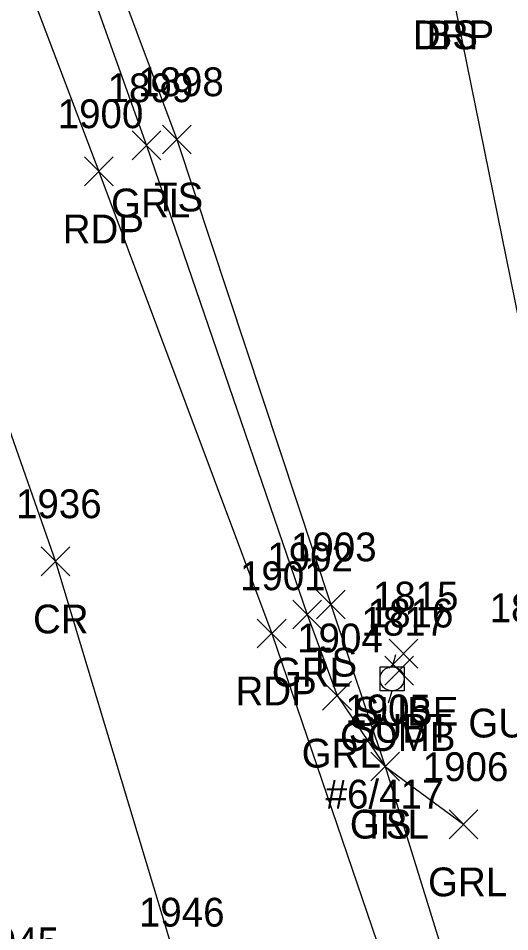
# Model space of a CAD drawing. Extents: x 1651305 to 1654558, y 539481 to 548441.
# Drawn here: x 1654361.1 to 1654395.2, y 544544.9 to 544608.3 of the extents above; entities that cross this region are included whole.
import ezdxf

# ---------------------------------------------------------------- set-up
doc = ezdxf.new("R2010")
doc.units = 0
for name, color, linetype in [('L_A', 7, 'Continuous'), ('L_I', 7, 'Continuous'), ('L_TIC', 7, 'Continuous'), ('LELB', 7, 'Continuous'), ('P_A', 7, 'Continuous'), ('P_I', 7, 'Continuous'), ('P_TIC', 7, 'Continuous'), ('PET', 7, 'Continuous'), ('PRC', 7, 'Continuous'), ('R_A', 7, 'Continuous'), ('R_I', 7, 'Continuous'), ('R_TIC', 7, 'Continuous'), ('RDP', 7, 'Continuous'), ('RGR', 7, 'Continuous'), ('U_A', 7, 'Continuous'), ('U_C', 7, 'Continuous'), ('U_I', 7, 'Continuous'), ('U_TIC', 7, 'Continuous'), ('UP', 7, 'Continuous')]:
    doc.layers.add(name, color=color, linetype=linetype)

msp = doc.modelspace()

# ---------------------------------------------------------------- linework, layer by layer
at = {"layer": 'L_TIC'}
for points in [[(1654371.116, 544598.924), (1654373.116, 544600.924)], [(1654373.116, 544598.924), (1654371.116, 544600.924)], [(1654381.811, 544566.633), (1654383.811, 544568.633)], [(1654383.811, 544566.633), (1654381.811, 544568.633)], [(1654385.584, 544555.384), (1654387.584, 544557.384)], [(1654387.584, 544555.384), (1654385.584, 544557.384)]]:
    msp.add_lwpolyline(points, dxfattribs=at)
at = {"layer": 'LELB'}
msp.add_lwpolyline([(1654360.198, 544631.754), (1654372.116, 544599.924), (1654382.811, 544567.633), (1654386.584, 544556.384), (1654391.723, 544539.804)], dxfattribs=at)
at = {"layer": 'P_TIC'}
for points in [[(1654365.692, 544596.705), (1654367.692, 544598.705)], [(1654367.692, 544596.705), (1654365.692, 544598.705)], [(1654362.685, 544569.628), (1654364.685, 544571.628)], [(1654364.685, 544569.628), (1654362.685, 544571.628)], [(1654377.699, 544564.627), (1654379.699, 544566.627)], [(1654379.699, 544564.627), (1654377.699, 544566.627)]]:
    msp.add_lwpolyline(points, dxfattribs=at)
at = {"layer": 'PET'}
msp.add_lwpolyline([(1654345.042, 544588.36), (1654350.59, 544607.191), (1654356.582, 544624.309), (1654366.692, 544597.705), (1654378.699, 544565.627), (1654388.798, 544536.019), (1654394.392, 544506.433), (1654399.121, 544481.008), (1654401.125, 544462.893), (1654401.531, 544436.346), (1654401.825, 544421.309), (1654397.366, 544359.696), (1654394.392, 544336.586), (1654391.404, 544308.963), (1654388.941, 544290.736), (1654386.845, 544274.06), (1654380.974, 544229.445), (1654377.749, 544202.908), (1654375.628, 544181.037), (1654372.192, 544149.754), (1654366.612, 544105.723), (1654362.798, 544072.788)], dxfattribs=at)
at = {"layer": 'PRC'}
msp.add_lwpolyline([(1654350.59, 544607.191), (1654355.931, 544592.699), (1654363.685, 544570.628), (1654372.223, 544542.272), (1654380.244, 544505.389), (1654384.95, 544473.916), (1654386.821, 544433.75), (1654385.713, 544395.522), (1654383.86, 544365.997), (1654380.919, 544339.646), (1654377.996, 544311.086), (1654373.889, 544274.842), (1654369.008, 544231.012), (1654366.63, 544212.463), (1654362.444, 544177.974), (1654359.488, 544151.886), (1654354.071, 544107.932), (1654348.42, 544063.008)], dxfattribs=at)
at = {"layer": 'R_TIC'}
for points in [[(1654368.998, 544598.511), (1654370.998, 544600.511)], [(1654370.998, 544598.511), (1654368.998, 544600.511)], [(1654380.164, 544565.937), (1654382.164, 544567.937)], [(1654382.164, 544565.937), (1654380.164, 544567.937)], [(1654382.241, 544560.31), (1654384.241, 544562.31)], [(1654384.241, 544560.31), (1654382.241, 544562.31)], [(1654385.584, 544555.384), (1654387.584, 544557.384)], [(1654387.584, 544555.384), (1654385.584, 544557.384)], [(1654391.02, 544551.375), (1654393.02, 544553.375)], [(1654393.02, 544551.375), (1654391.02, 544553.375)]]:
    msp.add_lwpolyline(points, dxfattribs=at)
at = {"layer": 'RDP'}
msp.add_lwpolyline([(1654389.401, 544756.56), (1654387.7, 544737.059), (1654385.299, 544704.988), (1654383.543, 544677.638), (1654384.483, 544660.968), (1654386.242, 544638.223), (1654391.022, 544611.182), (1654397.72, 544578.233), (1654402.202, 544552.331), (1654401.972, 544539.048), (1654399.157, 544531.466), (1654397.052, 544530.18)], dxfattribs=at)
at = {"layer": 'RGR'}
msp.add_lwpolyline([(1654358.986, 544630.265), (1654369.998, 544599.511), (1654381.164, 544566.937), (1654383.241, 544561.31), (1654386.584, 544556.384), (1654392.02, 544552.375)], dxfattribs=at)
at = {"layer": 'U_TIC'}
for points in [[(1654386.85, 544563.222), (1654388.85, 544565.222)], [(1654388.85, 544563.222), (1654386.85, 544565.222)], [(1654386.555, 544562.039), (1654388.555, 544564.039)], [(1654388.555, 544562.039), (1654386.555, 544564.039)]]:
    msp.add_lwpolyline(points, dxfattribs=at)
at = {"layer": 'UP'}
for p, q in [((1654387.31, 544564.138), (1654387.06, 544563.304)), ((1654386.227, 544561.638), (1654386.227, 544563.304)), ((1654386.227, 544563.304), (1654387.894, 544563.304)), ((1654387.894, 544563.304), (1654387.894, 544561.638)), ((1654387.06, 544562.471), (1654387.06, 544562.471)), ((1654387.894, 544561.638), (1654386.227, 544561.638)), ((1654386.81, 544560.804), (1654387.06, 544561.638))]:
    msp.add_line(p, q, dxfattribs=at)
msp.add_circle((1654387.06, 544562.471), 0.833, dxfattribs=at)

# ---------------------------------------------------------------- texts
at = {"layer": 'L_A'}
for s, p in [('BS', (1654389.462, 544606.182)), ('TS', (1654370.526, 544594.924)), ('TS', (1654381.221, 544562.633)), ('TS', (1654384.994, 544551.384))]:
    msp.add_text(s, height=2, dxfattribs=at).set_placement(p)
at = {"layer": 'L_I'}
for s, p in [('1898', (1654369.424, 544602.924)), ('1903', (1654380.04, 544570.633)), ('1905', (1654383.813, 544559.384))]:
    msp.add_text(s, height=2, dxfattribs=at).set_placement(p)
at = {"layer": 'P_A'}
for s, p in [('RDP', (1654364.18, 544592.705)), ('CR', (1654362.118, 544565.628)), ('RDP', (1654376.188, 544560.627))]:
    msp.add_text(s, height=2, dxfattribs=at).set_placement(p)
at = {"layer": 'P_I'}
for s, p in [('1900', (1654363.834, 544600.705)), ('1936', (1654360.937, 544573.628)), ('1901', (1654376.495, 544568.627)), ('1946', (1654369.475, 544545.272)), ('1945', (1654357.976, 544543.213))]:
    msp.add_text(s, height=2, dxfattribs=at).set_placement(p)
at = {"layer": 'R_A'}
for s, p in [('DRP', (1654388.51, 544606.182)), ('GRL', (1654367.541, 544594.511)), ('GRL', (1654378.708, 544561.937)), ('GRL', (1654380.784, 544556.31)), ('GRL', (1654384.128, 544551.384)), ('GRL', (1654389.563, 544547.375))]:
    msp.add_text(s, height=2, dxfattribs=at).set_placement(p)
at = {"layer": 'R_I'}
for s, p in [('1899', (1654367.297, 544602.511)), ('1902', (1654378.393, 544569.937)), ('1904', (1654380.47, 544564.31)), ('1905', (1654383.813, 544559.384)), ('1906', (1654389.193, 544555.375))]:
    msp.add_text(s, height=2, dxfattribs=at).set_placement(p)
at = {"layer": 'U_A'}
for s, p in [('SUBE', (1654384.386, 544559.222)), ('GUYW', (1654392.361, 544558.403)), ('SUBT', (1654384.051, 544558.039)), ('COMB', (1654383.446, 544557.471))]:
    msp.add_text(s, height=2, dxfattribs=at).set_placement(p)
at = {"layer": 'U_C'}
msp.add_text('#6/417', height=2, dxfattribs=at).set_placement((1654382.446, 544553.471))
at = {"layer": 'U_I'}
for s, p in [('1815', (1654385.725, 544567.222)), ('1816', (1654385.374, 544566.039)), ('1814', (1654393.841, 544566.403)), ('1817', (1654384.935, 544565.471))]:
    msp.add_text(s, height=2, dxfattribs=at).set_placement(p)

doc.saveas('drawing.dxf')
